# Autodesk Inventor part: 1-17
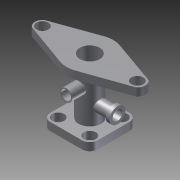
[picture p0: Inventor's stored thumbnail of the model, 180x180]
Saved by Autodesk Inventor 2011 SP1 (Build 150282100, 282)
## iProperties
Created: 2014-02
Part Number: 1-17
Document SubType Name: Modeling
Designer: Administrator
Density: 1 g/cm^3
Author: Administrator
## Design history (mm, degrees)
sketch "草图1"
  geometry: L1 (-6, 6)-(6, 6); L2 (6, 6)-(6, -6); L3 (6, -6)-(-6, -6); L4 (-6, -6)-(-6, 6); 3 further points
  constraints: 8 end point, 2 midpoint, 2 parallel, 1 horizontal, 1 horizontal alignment, 1 perpendicular, 1 vertical alignment
  dimensions: "d0" = 12 distance of L1.end L2.end; "d1" = 12 distance of L2.end L3.end
extrude "拉伸1" new body sketch "草图1" distance "d2" = 2; taper "d3" = 0 deg
fillet "圆角1" dims "d4" = 2
sketch "草图2"
  geometry: C1 r 2.827 at (0, 0); 1 further point
  constraints: 1 centre point, 1 coincident
extrude "拉伸2" join sketch "草图2" distance "d5" = 12; taper "d6" = 0 deg
sketch "草图3"
  geometry: L1 (-13.054, 1.573)-(-1.999, 5.553); L2 (13.307, 1.573)-(1.96, 5.567); L3 (-13.054, -1.573)-(-1.999, -5.553); L4 (13.307, -1.573)-(1.96, -5.567); C1 r 2.827 at (0, 0) reference; A1 r 1.907 centre (-11.976, 0) between (-13.054, 1.573) and (-13.054, -1.573); A2 r 2.052 centre (11.989, 0) between (13.307, -1.573) and (13.307, 1.573); A3 r 5.902 centre (0, 0) between (-1.999, -5.553) and (1.96, -5.567); A4 r 5.902 centre (0, 0) between (1.96, 5.567) and (-1.999, 5.553)
  constraints: 8 end point, 8 point on circle, 4 centre point, 4 tangent, 1 coincident
extrude "拉伸3" join sketch "草图3" distance "d7" = 2; taper "d8" = 0 deg
sketch "草图4"
  geometry: C1 r 1.5 at (-11.976, 0); C2 r 1.5 at (11.989, 0); A1 r 1.907 centre (-11.976, 0) between (-13.054, 1.573) and (-13.054, -1.573) reference; A2 r 2.052 centre (11.989, 0) between (13.307, -1.573) and (13.307, 1.573) reference
  constraints: 2 centre point, 2 coincident
  dimensions: "d9" = 3 diameter of C1; "d10" = 3 diameter of C2
extrude "拉伸4" cut sketch "草图4" distance "d11" = 2; taper "d12" = 0 deg
sketch "草图5"
  geometry: C1 r 1.5 at (4, 4); C2 r 1.5 at (4, -4); C3 r 1.5 at (-4, -4); C4 r 1.5 at (-4, 4); A1 r 2 centre (-4, -4) between (-6, -4) and (-4, -6) reference; A2 r 2 centre (4, -4) between (4, -6) and (6, -4) reference; A3 r 2 centre (4, 4) between (6, 4) and (4, 6) reference; A4 r 2 centre (-4, 4) between (-4, 6) and (-6, 4) reference
  constraints: 4 centre point, 4 coincident
  dimensions: "d13" = 3 diameter of C1; "d14" = 3 diameter of C2; "d15" = 3 diameter of C3; "d16" = 3 diameter of C4
extrude "拉伸5" cut sketch "草图5" stored distance "d17" = 2; taper "d18" = 0 deg
sketch "草图6"
  geometry: C1 r 2.827 at (0, 0) reference; C2 r 2.5 at (0, 0)
  constraints: 1 centre point, 1 coincident
  dimensions: "d19" = 5 diameter of C2
extrude "拉伸6" cut sketch "草图6" stored distance "d20" = 2; taper "d21" = 0 deg
sketch "草图7"
  geometry: C1 r 1.5 at (4, 9.884); 1 further point
  constraints: 1 centre point
  dimensions: "d22" = 3 diameter of C1
extrude "拉伸7" join sketch "草图7" stored distance "d23" = 2; taper "d24" = 0 deg
sketch "草图8"
  geometry: C1 r 1.5 at (0, 0) reference; C2 r 1.25 at (0, 0); 1 further point
  constraints: 1 centre point, 1 coincident
  dimensions: "d25" = 2.5 diameter of C2
extrude "拉伸8" cut sketch "草图8" stored distance "d26" = 2; taper "d27" = 0 deg
sketch "草图9"
  geometry: C1 r 1.5 at (-5.978, 4); 1 further point
  constraints: 1 centre point
  dimensions: "d28" = 3 diameter of C1
extrude "拉伸9" join sketch "草图9" stored distance "d29" = 2; taper "d30" = 0 deg
sketch "草图10"
  geometry: C1 r 1.5 at (0, 0) reference; C2 r 2 at (0, 0); 1 further point
  constraints: 1 centre point, 1 coincident
  dimensions: "d31" = 4 diameter of C2
extrude "拉伸10" join sketch "草图10" distance "d32" = 1; taper "d33" = 0 deg
sketch "草图11"
  geometry: C1 r 2 at (0, 0) reference; C2 r 1.25 at (0, 0); 1 further point
  constraints: 1 centre point, 1 coincident
  dimensions: "d34" = 2.5 diameter of C2
extrude "拉伸11" cut sketch "草图11" stored distance "d35" = 1; taper "d36" = 0 deg
node "实体1"
